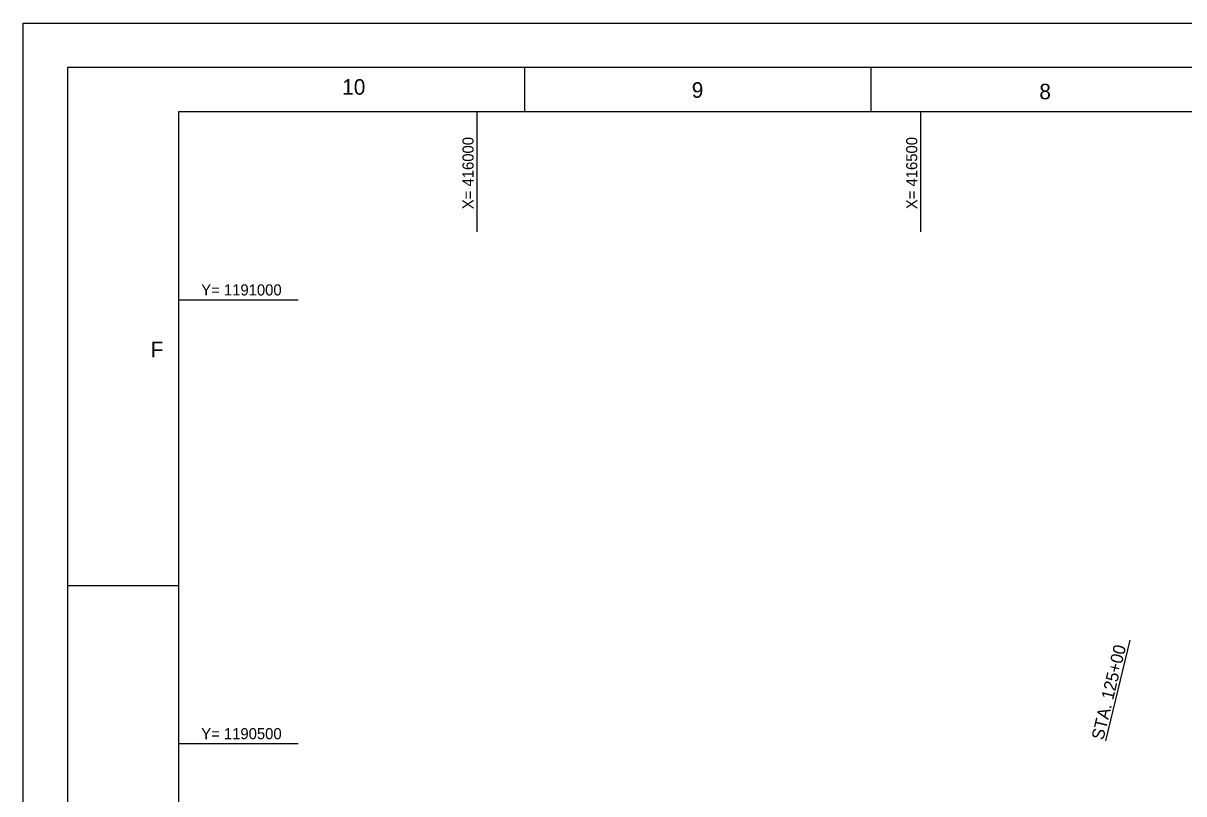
# Model space of a CAD drawing. Extents: x 415488 to 419888, y 1187739 to 1191312.
# Drawn here: x 415488 to 416796, y 1190444 to 1191312 of the extents above; entities that cross this region are included whole.
import ezdxf

# ---------------------------------------------------------------- set-up
doc = ezdxf.new("R2010")
doc.units = 0
for name, color, linetype in [('G-ANNO-NPLT', 7, 'Continuous'), ('G-ANNO-TTLB', 7, 'Continuous'), ('V-ALGN-TEXT', 7, 'Continuous'), ('V-TOPO-COOR-STAT', 7, 'Continuous')]:
    doc.layers.add(name, color=color, linetype=linetype)

msp = doc.modelspace()

# ---------------------------------------------------------------- linework, layer by layer
at = {"layer": 'G-ANNO-NPLT'}
msp.add_lwpolyline([(415488.5, 1191311.7), (419888.5, 1191311.7), (419888.5, 1187911.7), (415488.5, 1187911.7)], close=True, dxfattribs=at)
msp.add_lwpolyline([(415488.5, 1191261.7), (415488.5, 1191311.7), (415538.5, 1191311.7)], dxfattribs=at)
at = {"layer": 'G-ANNO-TTLB'}
for p, q in [((416053.5, 1191261.7), (416053.5, 1191211.7)), ((416443.5, 1191261.7), (416443.5, 1191211.7)), ((416443.5, 1191261.7), (416443.5, 1191211.7)), ((415538.5, 1190678.2), (415663.5, 1190678.2))]:
    msp.add_line(p, q, dxfattribs=at)
for points in [[(415538.5, 1187961.7), (419838.5, 1187961.7), (419838.5, 1191261.7), (415538.5, 1191261.7)], [(419788.5, 1191211.7), (415663.5, 1191211.7), (415663.5, 1188011.7), (419788.5, 1188011.7)]]:
    msp.add_lwpolyline(points, close=True, dxfattribs=at)
at = {"layer": 'V-ALGN-TEXT'}
msp.add_line((416708.5, 1190503.1), (416736.1, 1190616.5), dxfattribs=at)
at = {"layer": 'V-TOPO-COOR-STAT'}
for p, q in [((416000, 1191076.7), (416000, 1191211.7)), ((416500, 1191076.7), (416500, 1191211.7)), ((415663.5, 1191000), (415798.5, 1191000)), ((415663.5, 1190500), (415798.5, 1190500))]:
    msp.add_line(p, q, dxfattribs=at)

# ---------------------------------------------------------------- texts
at = {"layer": 'G-ANNO-TTLB'}
for s, p in [('10', (415848, 1191231.2)), ('9', (416241.9, 1191227.7)), ('8', (416633.6, 1191226)), ('F', (415632, 1190935.4))]:
    msp.add_text(s, height=17.5, dxfattribs=at).set_placement(p)
at = {"layer": 'V-ALGN-TEXT'}
msp.add_text('STA. 125+00', height=13.92, rotation=76.2946, dxfattribs=at).set_placement((416705.6, 1190503.3))
at = {"layer": 'V-TOPO-COOR-STAT'}
for s, p in [('X= 416000', (415996, 1191102.2)), ('X= 416500', (416496, 1191102.2))]:
    msp.add_text(s, height=12.5, rotation=90, dxfattribs=at).set_placement(p)
for s, p in [('Y= 1191000', (415689.1, 1191005)), ('Y= 1190500', (415689.1, 1190505))]:
    msp.add_text(s, height=12.5, dxfattribs=at).set_placement(p)

doc.saveas('drawing.dxf')
